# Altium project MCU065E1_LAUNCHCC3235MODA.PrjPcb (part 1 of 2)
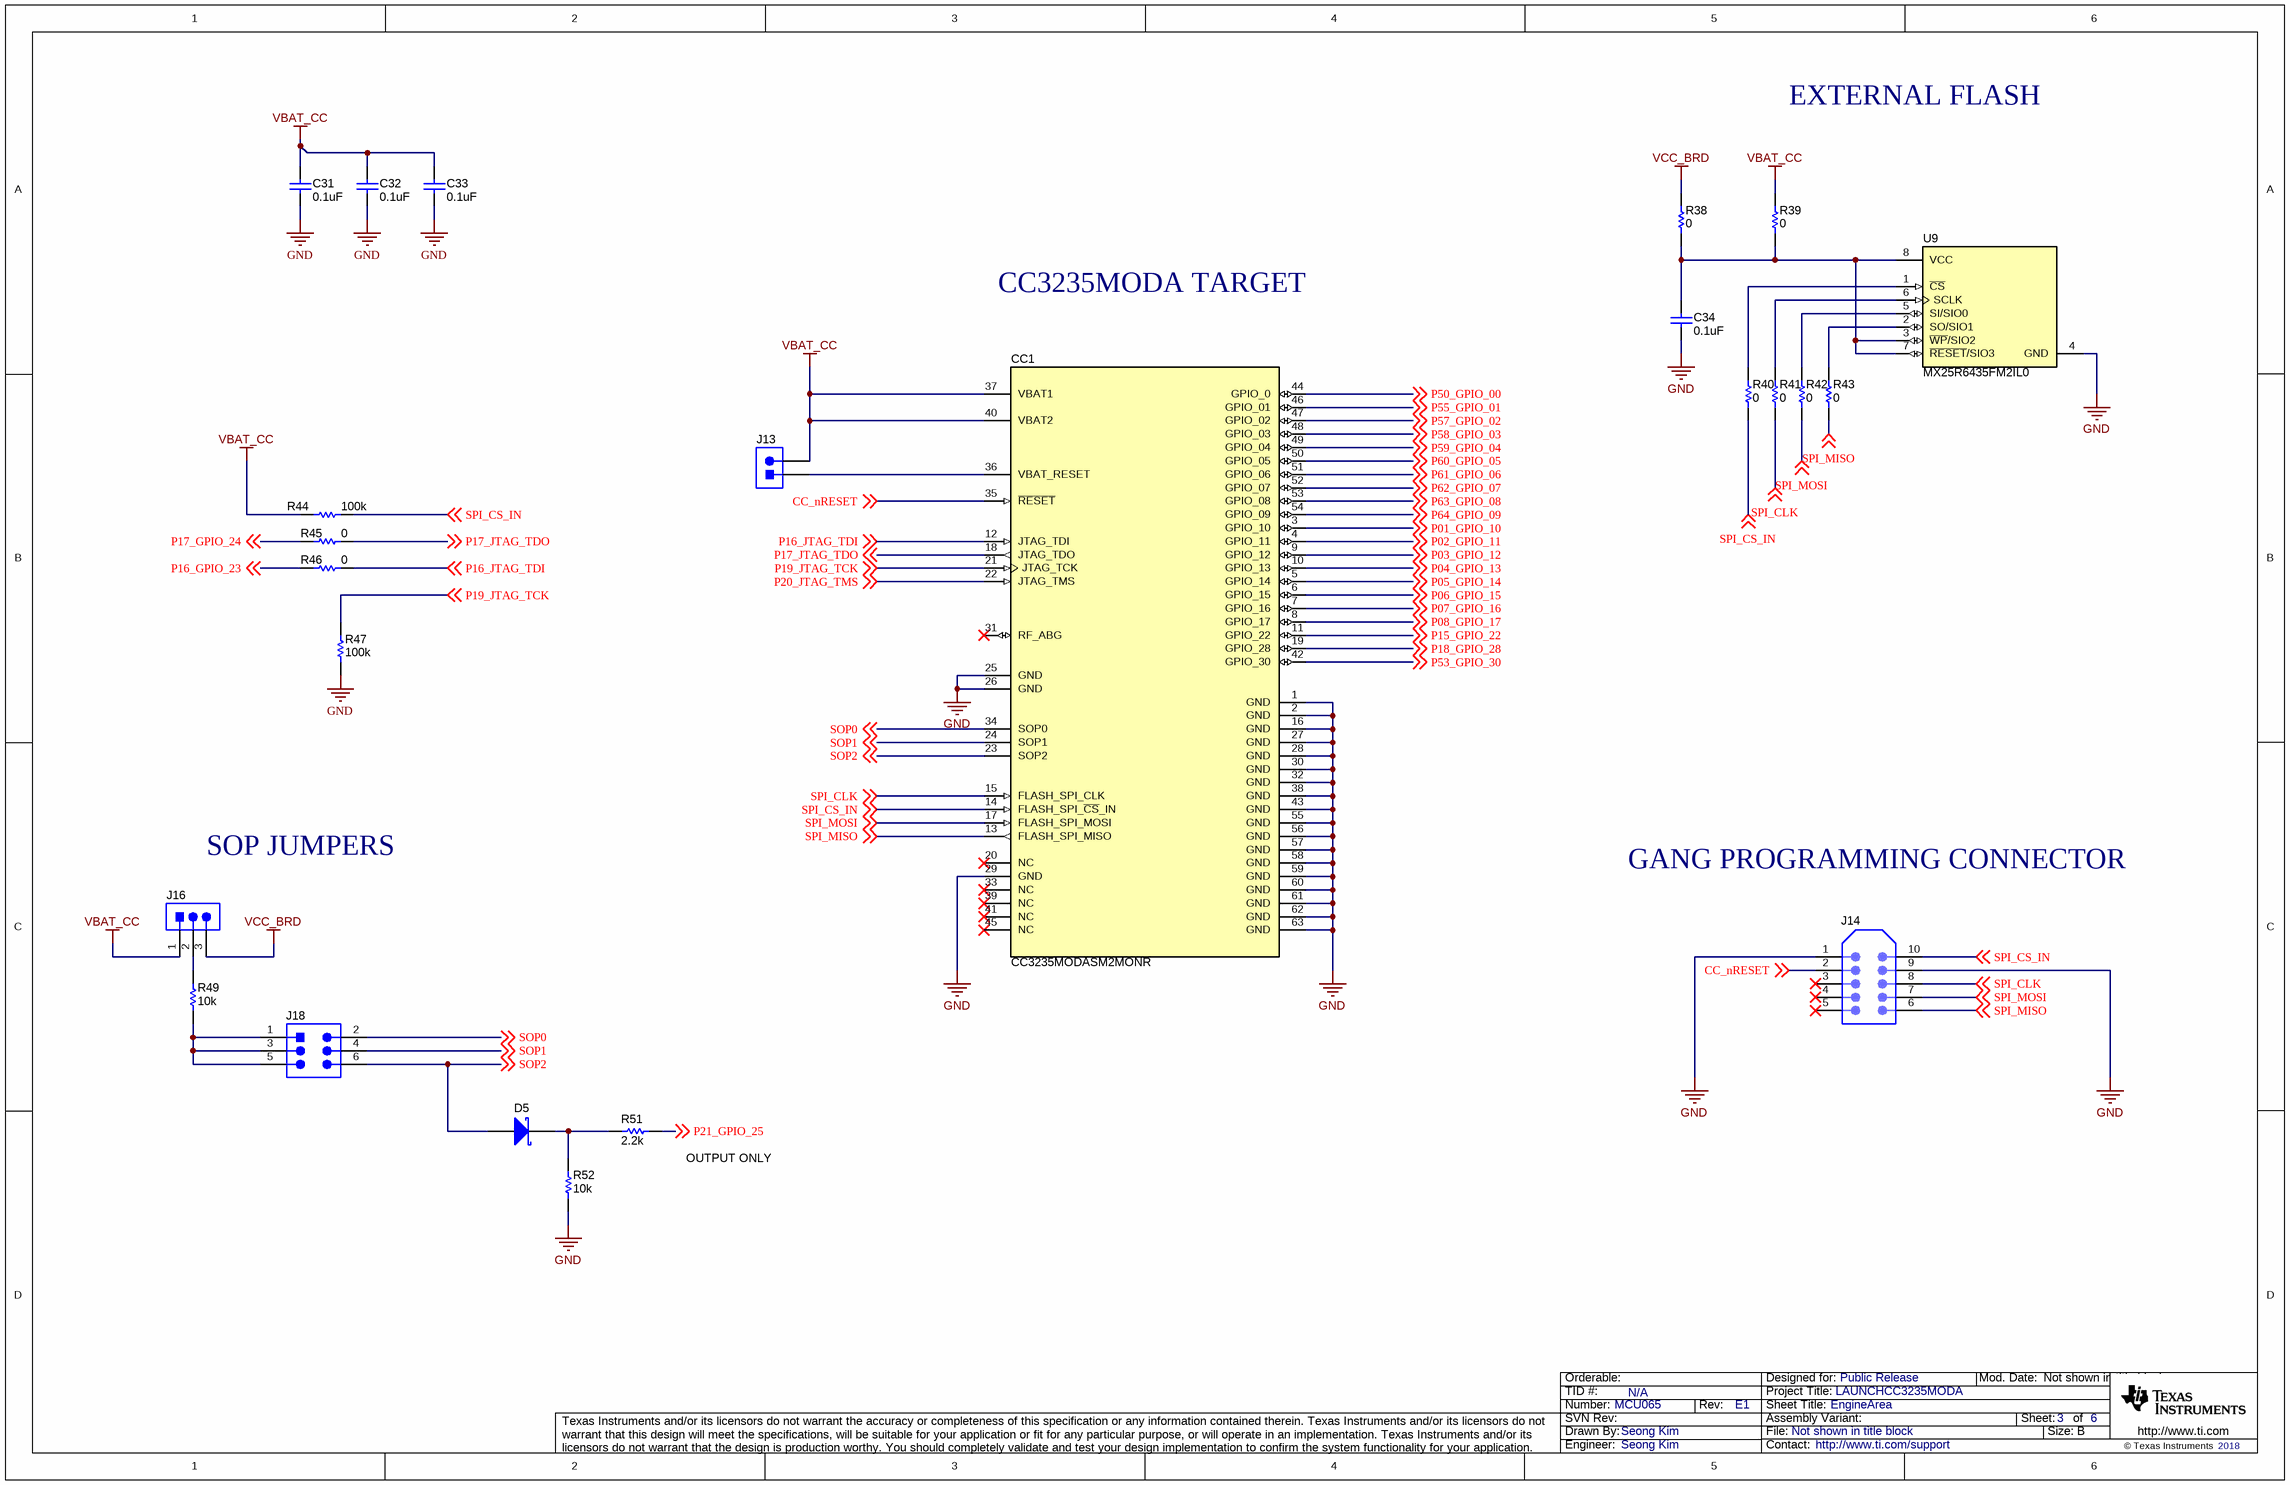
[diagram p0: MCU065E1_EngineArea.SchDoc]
CopyrightYear: 2018; PCB_Layout: Seong Kim; PCB_Rev: E1; PRJ_Customer: Public Release; PRJ_Engineer: Seong Kim; PRJ_Number: MCU065; PRJ_Title: LAUNCHCC3235MODA; SCH_Rev: E1; TechSupport: http://www.ti.com/support; TID: N/A
6 sheets, 301 parts. Net scope: global (net labels, ports and power ports of the same name join across sheets).
Board file: MCU065E1_LAUNCHCC3235MODA_PCB.PcbDoc
Sheets:
  MCU065E1_EngineArea.SchDoc
  MCU065E1_Hardware.SchDoc
  MCU065E1_Host_Interface.SchDoc
  MCU065E1_LEDs_Switches_Sensors.SchDoc
  MCU065E1_XDS110_Circuit.SchDoc
  MCU065E1_XDS110_Host.SchDoc

## Sheet MCU065E1_EngineArea.SchDoc: EngineArea
size 431 x 279 mm; Date: Not shown in title block; ApprovedBy: Not shown in title block; CheckedBy: Not shown in title block; Author: Not shown in title block; CompanyName: Not shown in title block; DrawnBy: Seong Kim; Engineer: Not shown in title block; Organization: Not shown in title block; Address1: Not shown in title block; Address2: Not shown in title block; Address3: Not shown in title block; Address4: Not shown in title block; DocumentNumber: 3; Revision: Use project parameter SCH_Rev; SheetNumber: 3; SheetTotal: 6; PageSetup: Record=PageOptions¦CenterHorizontal=True¦CenterVertical=True¦PrintScale=1.00¦XCorrection=1.00¦YCorrection=1.00¦PrintKind=0¦BorderSize=5000000¦LeftOffset=0¦BottomOffset=0¦Orientation=2¦PaperLength=1000¦PaperWidth=1000¦Scale=100¦PaperSource=15¦PrintQuality=600¦MediaType=1¦DitherType=10¦PaperKind=Letter¦PrintScaleMode=1

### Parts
C31  ValueDisplayed: 0.1uF  [0402]  (hidden comment: GRM155R61A104KA01D)
C32  ValueDisplayed: 0.1uF  [0402]  (hidden comment: GRM155R61A104KA01D)
C33  ValueDisplayed: 0.1uF  [0402]  (hidden comment: GRM155R61A104KA01D)
C34  ValueDisplayed: 0.1uF  [0402]  (hidden comment: GRM155R61A104KA01D)
CC1  CC3235MODASM2MONR  [MON0063A]
D5  CDBU00340  [SOD-523F]  (value not drawn)
J13  961102-6404-AR  [3M_961102-6404-AR]  (value not drawn)
J14  TC2050-IDC-NL-FP  [Tag_TC2050-NL]  (value not drawn)  (no BOM)
J16  CMP-0054796-1  [WURTH_61300311121]  (value not drawn)
J18  61300621121  [Wurth_61300621121]  (value not drawn)
R38  ValueDisplayed: 0  [0402]  (hidden comment: ERJ-2GE0R00X)
R39  ValueDisplayed: 0  [0402]  (hidden comment: ERJ-2GE0R00X)
R40  ValueDisplayed: 0  [0402]  (hidden comment: ERJ-2GE0R00X)
R41  ValueDisplayed: 0  [0402]  (hidden comment: ERJ-2GE0R00X)
R42  ValueDisplayed: 0  [0402]  (hidden comment: ERJ-2GE0R00X)
R43  ValueDisplayed: 0  [0402]  (hidden comment: ERJ-2GE0R00X)
R44  ValueDisplayed: 100k  [0402]  (hidden comment: CRCW0402100KDHEDP)
R45  ValueDisplayed: 0  [0402]  (hidden comment: ERJ-2GE0R00X)
R46  ValueDisplayed: 0  [0402]  (hidden comment: ERJ-2GE0R00X)
R47  ValueDisplayed: 100k  [0402]  (hidden comment: CRCW0402100KJNED)
R49  ValueDisplayed: 10k  [0402]  (hidden comment: CRCW040210K0JNED)
R51  ValueDisplayed: 2.2k  [0402]  (hidden comment: CRCW04022K20JNED)
R52  ValueDisplayed: 10k  [0402]  (hidden comment: CRCW040210K0JNED)
U9  MX25R6435FM2IL0  [SOP-8_200MIL]

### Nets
GND: C31.2 C32.2 C33.2 C34.2 CC1.1(GND) CC1.2(GND) CC1.16(GND) CC1.25(GND) CC1.26(GND) CC1.27(GND) CC1.28(GND) CC1.29(GND) CC1.30(GND) CC1.32(GND) CC1.38(GND) CC1.43(GND) CC1.55(GND) CC1.56(GND) CC1.57(GND) CC1.58(GND) CC1.59(GND) CC1.60(GND) CC1.61(GND) CC1.62(GND) CC1.63(GND) J14.1 J14.9 R47.1 R52.1 U9.4(GND)
VBAT_CC: C31.1 C32.1 C33.1 CC1.37(VBAT1) CC1.40(VBAT2) J13.2 J16.1 R39.2 R44.1
VCC_BRD: J16.3 R38.2
CC_nRESET: CC1.35(~{RESET}) J14.2 ; off-sheet CC_nRESET
P01_GPIO_10: CC1.3(GPIO_10) ; off-sheet P01_GPIO_10
P02_GPIO_11: CC1.4(GPIO_11) ; off-sheet P02_GPIO_11
P03_GPIO_12: CC1.9(GPIO_12) ; off-sheet P03_GPIO_12
P04_GPIO_13: CC1.10(GPIO_13) ; off-sheet P04_GPIO_13
P05_GPIO_14: CC1.5(GPIO_14) ; off-sheet P05_GPIO_14
P06_GPIO_15: CC1.6(GPIO_15) ; off-sheet P06_GPIO_15
P07_GPIO_16: CC1.7(GPIO_16) ; off-sheet P07_GPIO_16
P08_GPIO_17: CC1.8(GPIO_17) ; off-sheet P08_GPIO_17
P15_GPIO_22: CC1.11(GPIO_22) ; off-sheet P15_GPIO_22
P16_GPIO_23: R46.1 ; off-sheet P16_GPIO_23
P16_JTAG_TDI: CC1.12(JTAG_TDI) R46.2 ; off-sheet P16_JTAG_TDI
P17_GPIO_24: R45.1 ; off-sheet P17_GPIO_24
P17_JTAG_TDO: CC1.18(JTAG_TDO) R45.2 ; off-sheet P17_JTAG_TDO
P18_GPIO_28: CC1.19(GPIO_28) ; off-sheet P18_GPIO_28
P19_JTAG_TCK: CC1.21(JTAG_TCK) R47.2 ; off-sheet P19_JTAG_TCK
P20_JTAG_TMS: CC1.22(JTAG_TMS) ; off-sheet P20_JTAG_TMS
P21_GPIO_25: R51.2 ; off-sheet P21_GPIO_25
P50_GPIO_00: CC1.44(GPIO_0) ; off-sheet P50_GPIO_00
P53_GPIO_30: CC1.42(GPIO_30) ; off-sheet P53_GPIO_30
P55_GPIO_01: CC1.46(GPIO_01) ; off-sheet P55_GPIO_01
P57_GPIO_02: CC1.47(GPIO_02) ; off-sheet P57_GPIO_02
P58_GPIO_03: CC1.48(GPIO_03) ; off-sheet P58_GPIO_03
P59_GPIO_04: CC1.49(GPIO_04) ; off-sheet P59_GPIO_04
P60_GPIO_05: CC1.50(GPIO_05) ; off-sheet P60_GPIO_05
P61_GPIO_06: CC1.51(GPIO_06) ; off-sheet P61_GPIO_06
P62_GPIO_07: CC1.52(GPIO_07) ; off-sheet P62_GPIO_07
P63_GPIO_08: CC1.53(GPIO_08) ; off-sheet P63_GPIO_08
P64_GPIO_09: CC1.54(GPIO_09) ; off-sheet P64_GPIO_09
SOP0: CC1.34(SOP0) J18.2 ; off-sheet SOP0
SOP1: CC1.24(SOP1) J18.4 ; off-sheet SOP1
SOP2: CC1.23(SOP2) D5.2(A) J18.6 ; off-sheet SOP2
SPI_CLK: CC1.15(FLASH_SPI_CLK) J14.8 R41.1 ; off-sheet SPI_CLK
SPI_CS_IN: CC1.14(FLASH_SPI_~{CS}_IN) J14.10 R40.1 R44.2 ; off-sheet SPI_CS_IN
SPI_MISO: CC1.13(FLASH_SPI_MISO) J14.6 R43.1 ; off-sheet SPI_MISO
SPI_MOSI: CC1.17(FLASH_SPI_MOSI) J14.7 R42.1 ; off-sheet SPI_MOSI
NetC34_1: C34.1 R38.1 R39.1 U9.3(~{WP}/SIO2) U9.7(~{RESET}/SIO3) U9.8(VCC)
NetCC1_36: CC1.36(VBAT_RESET) J13.1
NetD5_1: D5.1(K) R51.1 R52.2
NetJ16_2: J16.2 R49.2
NetJ18_1: J18.1 J18.3 J18.5 R49.1
NetR40_2: R40.2 U9.1(~{CS})
NetR41_2: R41.2 U9.6(SCLK)
NetR42_2: R42.2 U9.5(SI/SIO0)
NetR43_2: R43.2 U9.2(SO/SIO1)

Not connected (* = marked no-connect by the designer): CC1 20(NC)* 31(RF_ABG)* 33(NC)* 39(NC)* 41(NC)* 45(NC)*; J14 3* 4* 5*

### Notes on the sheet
- EXTERNAL FLASH
- CC3235MODA TARGET
- SOP JUMPERS
- GANG PROGRAMMING CONNECTOR
- (near R51) OUTPUT ONLY

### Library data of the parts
C31-C34 = CMP-0006562-2: CAP, CERM, 0.1 uF, 10 V, +/- 10%, X5R, 0402; Manufacturer: MuRata; TaMin_C: -55°C; Polarized: N; SizeAreaWB_mm2: 3; Value1: Unknown; U/M: EA; Value: 0.1uF; TaMax_C: 85°C; SizeZ_mm: 0.6; SizeX_mm: 1; SizeY_mm: 0.5; Value2: 10V; CompType: Capacitor; Cap_F: 100nF; AEC Category: Q200
CC1 = CMP-0085200-1: SimpleLink Wi-FI and Internet-of-Things Dual Band Module Solution, a Single-Chip Wireless MCU, MON0063A (QFM-63); Alternate Manufacturer: Texas Instruments; SizeX_mm: 25.5; AEC Category: Q200; CompType: IC; SizeArea_mm2: 522.75; SizeY_mm: 20.5; SizeZ_mm: 2.45; AEC Qualified: N; SizeAreaWB_mm2: 618.75
D5 = CMP-0081923-1: Diode, Schottky, 45 V, 0.03 A, SOD-523F; Manufacturer: Comchip Technology; Io_A: 30mA; SizeAreaWB_mm2: 5.13; Vr_V: 45V; Value1: 0.03A; TJmax_C: 125°C; Value: 45V; SizeZ_mm: 0.85; SizeX_mm: 1.7; SizeY_mm: 0.9; Vf_V: 370mV; Value2: 0.37V; SizeArea_mm2: 1.53; AEC Qualified: N; AEC Category: Q101
J13 = CMP-0075197-1: Header, 2.54mm, 2x1, TH; Manufacturer: 3M; CNHeader: True; Current_A: 2A; Green_Lifecycle: Active; Shrouded: N; Gender: Male; Green_REACh: Passed; Voltage_V: 1kV; Row_Count: 1; Pitch_mm: 2.54; ContactFinish: Gold; CT: False; Cert_UL: Y
J14 = CMP-0075101-1: Footprint for Tag-Connect TC2050 No-Legs cables; Note: Footprint only, to mate with Tag-Connect TC2050 No-Legs cables; CT: False; CompType: Receptacle
J16 = CMP-0054796-1: Header, 2.54 mm, 3x1, Gold, TH; PartNumber: 61300311121; Manufacturer: Wurth Elektronik; CNHeader: TRUE; Green_Lifecycle: Active; Green_REACh: Passed; CT: FALSE
J18 = CMP-0054802-2: Header, 2.54mm, 3x2, Gold, TH; Manufacturer: Wurth Elektronik; Green_Lifecycle: Active; Shrouded: N; Gender: Male; Green_REACh: Passed; Row_Count: 2; RowSpacing_mm: 2.54
R38-R43 R45 R46 = CMP-0026992-3: RES, 0, 5%, 0.1 W, AEC-Q200 Grade 0, 0402; Manufacturer: Panasonic; Power_W: 100mW; TempCo: 600 ppm/C; Value_Code: 0000; Value: 0; EIA_Code: E24; SizeX_mm: 1; SizeY_mm: 0.5; SizeZ_mm: 0.6; Value2: 0.1W; CompType: Resistor; AEC Qualified: Y; VDC_V: 50V; AEC Category: Q200; SizeAreaWB_mm2: 3
R44 = CMP-0026768-2: RES, 100 k, 0.5%, 0.063 W, AEC-Q200 Grade 0, 0402; Manufacturer: Vishay-Dale; Power_W: 63mW; TempCo: 50 ppm/C; Value: 100k; EIA_Code: E192; SizeX_mm: 1; SizeY_mm: 0.5; SizeZ_mm: 0.6; Value2: 0.063W; CompType: Resistor; AEC Qualified: Y; VDC_V: 50V; AEC Category: Q200; AEC Grade: 0
R47 = CMP-0026823-3: RES, 100 k, 5%, 0.063 W, AEC-Q200 Grade 0, 0402; Manufacturer: Vishay-Dale; Power_W: 63mW; TempCo: 200 ppm/C; Value: 100k; EIA_Code: E24; SizeX_mm: 1; SizeY_mm: 0.5; SizeZ_mm: 0.6; Value2: 0.063W; CompType: Resistor; AEC Qualified: Y; VDC_V: 50V; AEC Category: Q200; AEC Grade: 0
R49 R52 = CMP-0026825-5: RES, 10 k, 5%, 0.063 W, AEC-Q200 Grade 0, 0402; Manufacturer: Vishay-Dale; Power_W: 63mW; TempCo: 200 ppm/C; Value_Code: 10k0; Value: 10k; EIA_Code: E24; SizeX_mm: 1; SizeY_mm: 0.5; SizeZ_mm: 0.6; Value2: 0.063W; CompType: Resistor; AEC Qualified: Y; VDC_V: 50V; AEC Category: Q200; AEC Grade: 0
R51 = CMP-0026890-5: RES, 2.2 k, 5%, 0.063 W, AEC-Q200 Grade 0, 0402; Manufacturer: Vishay-Dale; Power_W: 63mW; TempCo: 200 ppm/C; Value_Code: 2k20; Value: 2.2k; EIA_Code: E24; SizeX_mm: 1; SizeY_mm: 0.5; SizeZ_mm: 0.6; Value2: 0.063W; CompType: Resistor; AEC Qualified: Y; VDC_V: 50V; AEC Category: Q200; AEC Grade: 0
U9 = CMP-0004983-1: ULTRA LOW POWER, 64M-BIT [x 1/x 2/x 4] CMOS MXSMIO (SERIAL MULTI I/O) FLASH MEMORY, SOP-8; Manufacturer: Macronix International Co., LTD; SizeZ_mm: 2.16; SizeX_mm: 7.9; SizeY_mm: 5.23; SizeArea_mm2: 41.317; SizeAreaWB_mm2: 71.577

## Sheet MCU065E1_Hardware.SchDoc: Hardware
size 431 x 279 mm; Date: Not shown in title block; ApprovedBy: Not shown in title block; CheckedBy: Not shown in title block; Author: Not shown in title block; CompanyName: Not shown in title block; DrawnBy: Seong Kim; Engineer: Not shown in title block; Organization: Not shown in title block; Address1: Not shown in title block; Address2: Not shown in title block; Address3: Not shown in title block; Address4: Not shown in title block; DocumentNumber: 6; Revision: Use project parameter SCH_Rev; SheetNumber: 6; SheetTotal: 6; PageSetup: Record=PageOptions¦CenterHorizontal=True¦CenterVertical=True¦PrintScale=1.00¦XCorrection=1.00¦YCorrection=1.00¦PrintKind=0¦BorderSize=5000000¦LeftOffset=0¦BottomOffset=0¦Orientation=2¦PaperLength=1000¦PaperWidth=1000¦Scale=100¦PaperSource=15¦PrintQuality=600¦MediaType=1¦DitherType=10¦PaperKind=Letter¦PrintScaleMode=1
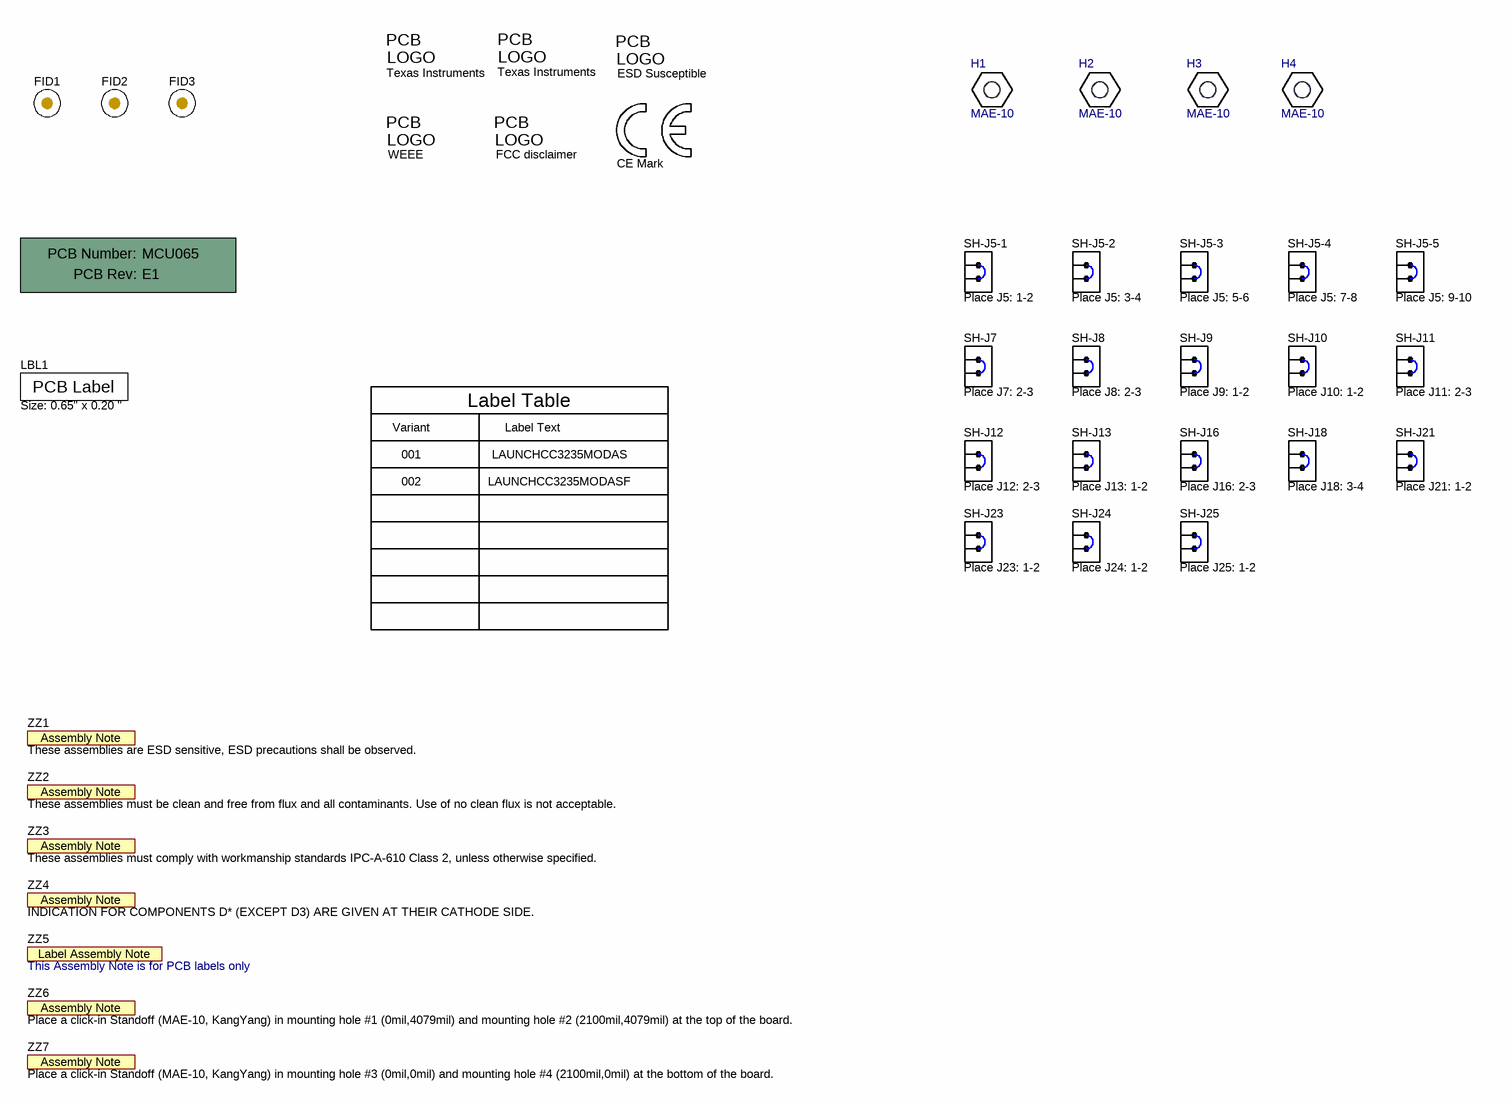
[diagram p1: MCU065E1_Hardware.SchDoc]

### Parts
!PCB1  Printed Circuit Board  (value not drawn)  (mechanical)
CE_Logo_1  CE Mark  [CE_Mark_5mm]  (no BOM)
FID1  CMP-0077181-1  [Fiducial10-20]  (value not drawn)  (no BOM)
FID2  CMP-0077181-1  [Fiducial10-20]  (value not drawn)  (no BOM)
FID3  CMP-0077181-1  [Fiducial10-20]  (value not drawn)  (no BOM)
H1  MAE-10  [KY_MAE-10]
H2  MAE-10  [KY_MAE-10]
H3  MAE-10  [KY_MAE-10]
H4  MAE-10  [KY_MAE-10]
LBL1  Size: 0.65" x 0.20 "  [Label_650x200]
Logo1  Texas Instruments  [TI_Symbol_Overlay_Medium]  (no BOM)
Logo2  ESD Susceptible  [ESD_Overlay_Medium]  (no BOM)
Logo3  WEEE  [WEEE_Minimum]  (no BOM)
Logo4  FCC disclaimer  [FCC_disclaimer]  (no BOM)
SH-J5-1  Place J5: 1-2  [SNT-100-BK-G]
SH-J5-2  Place J5: 3-4  [SNT-100-BK-G]
SH-J5-3  Place J5: 5-6  [SNT-100-BK-G]
SH-J5-4  Place J5: 7-8  [SNT-100-BK-G]
SH-J5-5  Place J5: 9-10  [SNT-100-BK-G]
SH-J7  Place J7: 2-3  [SNT-100-BK-G]
SH-J8  Place J8: 2-3  [SNT-100-BK-G]
SH-J9  Place J9: 1-2  [SNT-100-BK-G]
SH-J10  Place J10: 1-2  [SNT-100-BK-G]
SH-J11  Place J11: 2-3  [SNT-100-BK-G]
SH-J12  Place J12: 2-3  [SNT-100-BK-G]
SH-J13  Place J13: 1-2  [SNT-100-BK-G]
SH-J16  Place J16: 2-3  [SNT-100-BK-G]
SH-J18  Place J18: 3-4  [SNT-100-BK-G]
SH-J21  Place J21: 1-2  [SNT-100-BK-G]
SH-J23  Place J23: 1-2  [SNT-100-BK-G]
SH-J24  Place J24: 1-2  [SNT-100-BK-G]
SH-J25  Place J25: 1-2  [SNT-100-BK-G]
TI_Logo_1  Texas Instruments  [TI_Stacked_Overlay_Medium]  (no BOM)
ZZ1  These assemblies are ESD sensitive, ESD precautions shall be observed.  [AssemblyNote]  (no BOM)
ZZ2  These assemblies must be clean and free from flux and all contaminants. Use of no clean flux is not acceptable.  [AssemblyNote]  (no BOM)
ZZ3  These assemblies must comply with workmanship standards IPC-A-610 Class 2, unless otherwise specified.  [AssemblyNote]  (no BOM)
ZZ4  INDICATION FOR COMPONENTS D* (EXCEPT D3) ARE GIVEN AT THEIR CATHODE SIDE.  [AssemblyNote]  (no BOM)
ZZ5  This Assembly Note is for PCB labels only  [AssemblyNoteLabel]  (no BOM)
ZZ6  Place a click-in Standoff (MAE-10, KangYang) in mounting hole #1 (0mil,4079mil) and mounting hole #2 (2100mil,4079mil) at the top of the board.  [AssemblyNote]  (no BOM)
ZZ7  Place a click-in Standoff (MAE-10, KangYang) in mounting hole #3 (0mil,0mil) and mounting hole #4 (2100mil,0mil) at the bottom of the board.  [AssemblyNote]  (no BOM)

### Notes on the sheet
- Label Table
- Variant
- 001
- Label Text
- LAUNCHCC3235MODAS
- 002
- LAUNCHCC3235MODASF

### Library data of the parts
!PCB1 = CMP-0003618-2: PartNumber: MCU065; Manufacturer: Any; CompType: PCB
CE_Logo_1 = CMP-0074844-1: SymbolCreator: a0412235
FID1-FID3 = CMP-0077181-1: Fiducial mark.  There is nothing to buy or mount.
H1-H4 = CMP-0077978-1: Spacer Support, Nylon 66; Manufacturer: Kang Yang; CompType: Standoff
LBL1 = CMP-0003625-1: Manufacturer: Brady; Key: THT-14-423-10; CompType: Label
Logo1 TI_Logo_1 = CMP-0074838-1: Texas Instrument Corporate Signature; Library Reference: Logo; SymbolCreator: a0412235; Lib Reference: TI_Logo
Logo2 = CMP-0074840-1: ESD Susceptible Symbol; Library Reference: Logo; SymbolCreator: a0412235; Lib Reference: ESD_Susceptible
Logo3 = CMP-0074769-1: WEEE logo
Logo4 = CMP-0074847-1: FCC_disclaimer; Library Reference: Logo
SH-J5-1-SH-J5-5 SH-J7-SH-J13 SH-J16 SH-J18 SH-J21 SH-J23-SH-J25 = CMP-0003623-3: Shunt, 100mil, Gold plated, Black; Alternate PartNumber: 969102-0000-DA; Manufacturer: Samtec; Alternate Manufacturer: 3M; Value: 1x2
ZZ1-ZZ3 = CMP-0077238-1: This Assembly Note will show in the PcbDoc and associated outputs
ZZ4 ZZ6 ZZ7 = CMP-0077238-1
ZZ5 = CMP-0003616-3

## Sheet MCU065E1_Host_Interface.SchDoc: Host_Interface
size 431 x 279 mm; Date: Not shown in title block; ApprovedBy: Not shown in title block; CheckedBy: Not shown in title block; Author: Not shown in title block; CompanyName: Not shown in title block; DrawnBy: Seong Kim; Engineer: Not shown in title block; Organization: Not shown in title block; Address1: Not shown in title block; Address2: Not shown in title block; Address3: Not shown in title block; Address4: Not shown in title block; DocumentNumber: 5; Revision: Use project parameter SCH_Rev; SheetNumber: 5; SheetTotal: 6; PageSetup: Record=PageOptions¦CenterHorizontal=True¦CenterVertical=True¦PrintScale=1.00¦XCorrection=1.00¦YCorrection=1.00¦PrintKind=0¦BorderSize=5000000¦LeftOffset=0¦BottomOffset=0¦Orientation=2¦PaperLength=1000¦PaperWidth=1000¦Scale=100¦PaperSource=15¦PrintQuality=600¦MediaType=1¦DitherType=10¦PaperKind=Letter¦PrintScaleMode=1
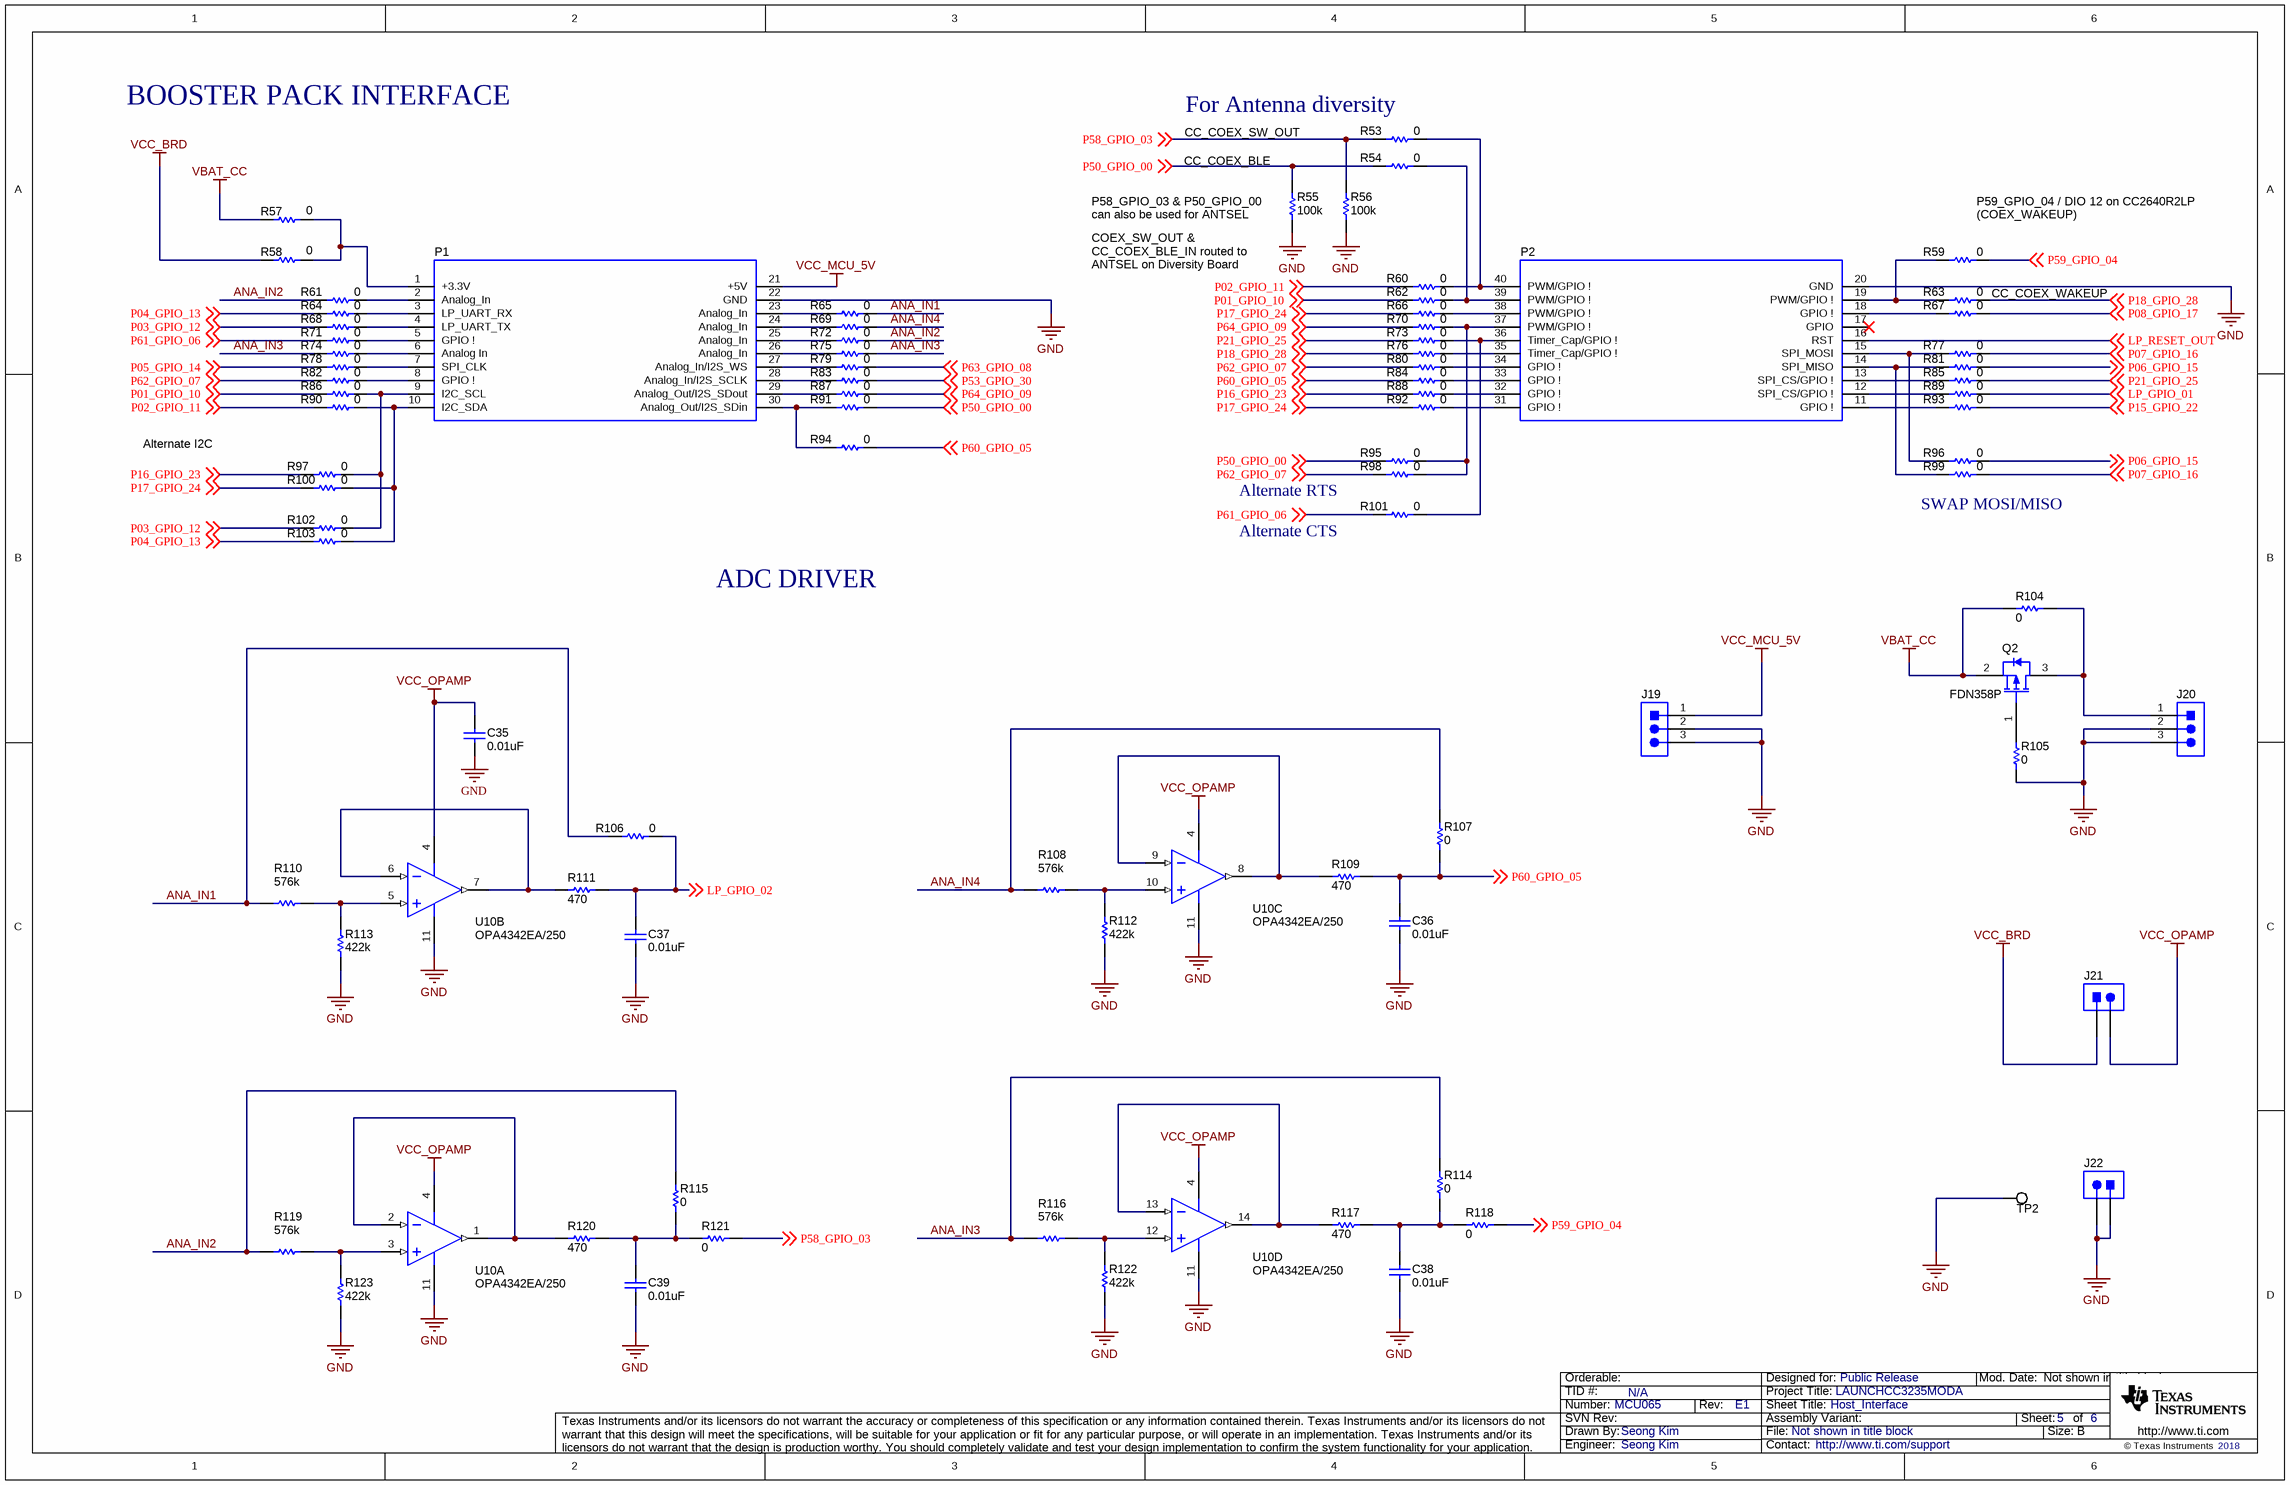
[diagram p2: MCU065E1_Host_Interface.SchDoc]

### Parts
C35  ValueDisplayed: 0.01uF  [0402]  (hidden comment: GRM155R61A103KA01D)
C36  ValueDisplayed: 0.01uF  [0402]  (hidden comment: GRM155R71C103KA01D)
C37  ValueDisplayed: 0.01uF  [0402]  (hidden comment: GRM155R71C103KA01D)
C38  ValueDisplayed: 0.01uF  [0402]  (hidden comment: GRM155R71C103KA01D)
C39  ValueDisplayed: 0.01uF  [0402]  (hidden comment: GRM155R71C103KA01D)
J19  PEC03SAAN  [CONN_PEC03SAAN]  (value not drawn)
J20  PEC03SAAN  [CONN_PEC03SAAN]  (value not drawn)
J21  CMP-0054794-1  [WURTH_61300211121]  (value not drawn)
J22  61300211121  [WURTH_61300211121]  (value not drawn)
P1  SSQ-110-03-T-D  [BoosterPack_40pin_J1J3]  (value not drawn)
P2  SSQ-110-03-T-D  [BoosterPack_40pin_J2J4]  (value not drawn)
Q2  FDN358P  [SSOT-3]
R53  ValueDisplayed: 0  [0402]  (hidden comment: RC0402JR-070RL)
R54  ValueDisplayed: 0  [0402]  (hidden comment: RC0402JR-070RL)
R55  ValueDisplayed: 100k  [0402]  (hidden comment: CMP-0026823-3)
R56  ValueDisplayed: 100k  [0402]  (hidden comment: CMP-0026823-3)
R57  ValueDisplayed: 0  [0603]  (hidden comment: CMP-0025874-3)
R58  ValueDisplayed: 0  [0603]  (hidden comment: CMP-0025874-3)
R59  ValueDisplayed: 0  [0402]  (hidden comment: RC0402JR-070RL)
R60  ValueDisplayed: 0  [0402]  (hidden comment: RC0402JR-070RL)
R61  ValueDisplayed: 0  [0402]  (hidden comment: RC0402JR-070RL)
R62  ValueDisplayed: 0  [0402]  (hidden comment: RC0402JR-070RL)
R63  ValueDisplayed: 0  [0402]  (hidden comment: RC0402JR-070RL)
R64  ValueDisplayed: 0  [0402]  (hidden comment: RC0402JR-070RL)
R65  ValueDisplayed: 0  [0402]  (hidden comment: RC0402JR-070RL)
R66  ValueDisplayed: 0  [0402]  (hidden comment: RC0402JR-070RL)
R67  ValueDisplayed: 0  [0402]  (hidden comment: RC0402JR-070RL)
R68  ValueDisplayed: 0  [0402]  (hidden comment: RC0402JR-070RL)
R69  ValueDisplayed: 0  [0402]  (hidden comment: RC0402JR-070RL)
R70  ValueDisplayed: 0  [0402]  (hidden comment: RC0402JR-070RL)
R71  ValueDisplayed: 0  [0402]  (hidden comment: RC0402JR-070RL)
R72  ValueDisplayed: 0  [0402]  (hidden comment: RC0402JR-070RL)
R73  ValueDisplayed: 0  [0402]  (hidden comment: RC0402JR-070RL)
R74  ValueDisplayed: 0  [0402]  (hidden comment: RC0402JR-070RL)
R75  ValueDisplayed: 0  [0402]  (hidden comment: RC0402JR-070RL)
R76  ValueDisplayed: 0  [0402]  (hidden comment: RC0402JR-070RL)
R77  ValueDisplayed: 0  [0402]  (hidden comment: RC0402JR-070RL)
R78  ValueDisplayed: 0  [0402]  (hidden comment: RC0402JR-070RL)
R79  ValueDisplayed: 0  [0402]  (hidden comment: RC0402JR-070RL)
R80  ValueDisplayed: 0  [0402]  (hidden comment: RC0402JR-070RL)
R81  ValueDisplayed: 0  [0402]  (hidden comment: RC0402JR-070RL)
R82  ValueDisplayed: 0  [0402]  (hidden comment: RC0402JR-070RL)
R83  ValueDisplayed: 0  [0402]  (hidden comment: RC0402JR-070RL)
R84  ValueDisplayed: 0  [0402]  (hidden comment: RC0402JR-070RL)
R85  ValueDisplayed: 0  [0402]  (hidden comment: RC0402JR-070RL)
R86  ValueDisplayed: 0  [0402]  (hidden comment: RC0402JR-070RL)
R87  ValueDisplayed: 0  [0402]  (hidden comment: RC0402JR-070RL)
R88  ValueDisplayed: 0  [0402]  (hidden comment: RC0402JR-070RL)
R89  ValueDisplayed: 0  [0402]  (hidden comment: RC0402JR-070RL)
R90  ValueDisplayed: 0  [0402]  (hidden comment: RC0402JR-070RL)
R91  ValueDisplayed: 0  [0402]  (hidden comment: RC0402JR-070RL)
R92  ValueDisplayed: 0  [0402]  (hidden comment: RC0402JR-070RL)
R93  ValueDisplayed: 0  [0402]  (hidden comment: RC0402JR-070RL)
R94  ValueDisplayed: 0  [0402]  (hidden comment: RC0402JR-070RL)
R95  ValueDisplayed: 0  [0402]  (hidden comment: RC0402JR-070RL)
R96  ValueDisplayed: 0  [0402]  (hidden comment: RC0402JR-070RL)
R97  ValueDisplayed: 0  [0402]  (hidden comment: RC0402JR-070RL)
R98  ValueDisplayed: 0  [0402]  (hidden comment: RC0402JR-070RL)
R99  ValueDisplayed: 0  [0402]  (hidden comment: RC0402JR-070RL)
R100  ValueDisplayed: 0  [0402]  (hidden comment: RC0402JR-070RL)
R101  ValueDisplayed: 0  [0402]  (hidden comment: RC0402JR-070RL)
R102  ValueDisplayed: 0  [0402]  (hidden comment: RC0402JR-070RL)
R103  ValueDisplayed: 0  [0402]  (hidden comment: RC0402JR-070RL)
R104  ValueDisplayed: 0  [0402]  (hidden comment: ERJ-2GE0R00X)
R105  ValueDisplayed: 0  [0402]  (hidden comment: ERJ-2GE0R00X)
R106  ValueDisplayed: 0  [0402]  (hidden comment: RC0402JR-070RL)
R107  ValueDisplayed: 0  [0402]  (hidden comment: RC0402JR-070RL)
R108  ValueDisplayed: 576k  [0402]  (hidden comment: CRCW0402576KFKED)
R109  ValueDisplayed: 470  [0402]  (hidden comment: ERJ-2RKF4700X)
R110  ValueDisplayed: 576k  [0402]  (hidden comment: CRCW0402576KFKED)
R111  ValueDisplayed: 470  [0402]  (hidden comment: ERJ-2RKF4700X)
R112  ValueDisplayed: 422k  [0402]  (hidden comment: CRCW0402422KFKED)
R113  ValueDisplayed: 422k  [0402]  (hidden comment: CRCW0402422KFKED)
R114  ValueDisplayed: 0  [0402]  (hidden comment: RC0402JR-070RL)
R115  ValueDisplayed: 0  [0402]  (hidden comment: RC0402JR-070RL)
R116  ValueDisplayed: 576k  [0402]  (hidden comment: CRCW0402576KFKED)
R117  ValueDisplayed: 470  [0402]  (hidden comment: ERJ-2RKF4700X)
R118  ValueDisplayed: 0  [0402]  (hidden comment: RC0402JR-070RL)
R119  ValueDisplayed: 576k  [0402]  (hidden comment: CRCW0402576KFKED)
R120  ValueDisplayed: 470  [0402]  (hidden comment: ERJ-2RKF4700X)
R121  ValueDisplayed: 0  [0402]  (hidden comment: RC0402JR-070RL)
R122  ValueDisplayed: 422k  [0402]  (hidden comment: CRCW0402422KFKED)
R123  ValueDisplayed: 422k  [0402]  (hidden comment: CRCW0402422KFKED)
TP2  5015  [Testpoint_Keystone_Miniature]  (value not drawn)
U10  OPA4342EA/250  [PW0014A_N]  (parts A,B,C,D of 4)

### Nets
GND: C35.2 C36.2 C37.2 C38.2 C39.2 J19.2 J19.3 J20.2 J20.3 J22.1 J22.2 P1.22(GND) P2.20(GND) R55.2 R56.2 R105.2 R112.1 R113.1 R122.1 R123.1 TP2.1 U10.11(V-)
VBAT_CC: Q2.2(S) R57.1 R104.2
VCC_BRD: J21.1 R58.1
VCC_MCU_5V: J19.1 P1.21(+5V)
VCC_OPAMP: C35.1 J21.2 U10.4(V+)
ANA_IN1: R65.2 R106.1 R110.1
ANA_IN2: R61.1 R72.2 R115.1 R119.1
ANA_IN3: R74.1 R75.2 R114.1 R116.1
ANA_IN4: R69.2 R107.1 R108.1
LP_GPIO_01: R89.2 ; off-sheet LP_GPIO_01
LP_GPIO_02: C37.1 R106.2 R111.2 ; off-sheet LP_GPIO_02
LP_RESET_OUT: P2.16(RST) ; off-sheet LP_RESET_OUT
P01_GPIO_10: R62.1 R86.1 ; off-sheet P01_GPIO_10
P02_GPIO_11: R60.1 R90.1 ; off-sheet P02_GPIO_11
P03_GPIO_12: R68.1 R102.1 ; off-sheet P03_GPIO_12
P04_GPIO_13: R64.1 R103.1 ; off-sheet P04_GPIO_13
P05_GPIO_14: R78.1 ; off-sheet P05_GPIO_14
P06_GPIO_15: R81.2 R96.2 ; off-sheet P06_GPIO_15
P07_GPIO_16: R77.2 R99.2 ; off-sheet P07_GPIO_16
P08_GPIO_17: R67.2 ; off-sheet P08_GPIO_17
P15_GPIO_22: R93.2 ; off-sheet P15_GPIO_22
P16_GPIO_23: R88.1 R97.1 ; off-sheet P16_GPIO_23
P17_GPIO_24: R66.1 R92.1 R100.1 ; off-sheet P17_GPIO_24
P18_GPIO_28: R63.2 R76.1 ; off-sheet P18_GPIO_28
P21_GPIO_25: R73.1 R85.2 ; off-sheet P21_GPIO_25
P50_GPIO_00: R54.1 R55.1 R91.2 R95.1 ; off-sheet P50_GPIO_00
P53_GPIO_30: R83.2 ; off-sheet P53_GPIO_30
P58_GPIO_03: R53.1 R56.1 R121.2 ; off-sheet P58_GPIO_03
P59_GPIO_04: R59.2 R118.2 ; off-sheet P59_GPIO_04
P60_GPIO_05: C36.1 R84.1 R94.2 R107.2 R109.2 ; off-sheet P60_GPIO_05
P61_GPIO_06: R71.1 R101.1 ; off-sheet P61_GPIO_06
P62_GPIO_07: R80.1 R82.1 R98.1 ; off-sheet P62_GPIO_07
P63_GPIO_08: R79.2 ; off-sheet P63_GPIO_08
P64_GPIO_09: R70.1 R87.2 ; off-sheet P64_GPIO_09
NetC38_1: C38.1 R114.2 R117.2 R118.1
NetC39_1: C39.1 R115.2 R120.2 R121.1
NetJ20_1: J20.1 Q2.3(D) R104.1
NetP1_1: P1.1(+3.3V) R57.2 R58.2
NetP1_2: P1.2(Analog_In) R61.2
NetP1_3: P1.3(LP_UART_RX) R64.2
NetP1_4: P1.4(LP_UART_TX) R68.2
NetP1_5: P1.5(GPIO_!) R71.2
NetP1_6: P1.6(Analog_In) R74.2
NetP1_7: P1.7(SPI_CLK) R78.2
NetP1_8: P1.8(GPIO_!) R82.2
NetP1_9: P1.9(I2C_SCL) R86.2 R97.2 R102.2
NetP1_10: P1.10(I2C_SDA) R90.2 R100.2 R103.2
NetP1_23: P1.23(Analog_In) R65.1
NetP1_24: P1.24(Analog_In) R69.1
NetP1_25: P1.25(Analog_In) R72.1
NetP1_26: P1.26(Analog_In) R75.1
NetP1_27: P1.27(Analog_In/I2S_WS) R79.1
NetP1_28: P1.28(Analog_In/I2S_SCLK) R83.1
NetP1_29: P1.29(Analog_Out/I2S_SDout) R87.1
NetP1_30: P1.30(Analog_Out/I2S_SDin) R91.1 R94.1
NetP2_11: P2.11(GPIO_!) R93.1
NetP2_12: P2.12(SPI_CS/GPIO_!) R89.1
NetP2_13: P2.13(SPI_CS/GPIO_!) R85.1
NetP2_14: P2.14(SPI_MISO) R81.1 R99.1
NetP2_15: P2.15(SPI_MOSI) R77.1 R96.1
NetP2_18: P2.18(GPIO_!) R67.1
NetP2_19: P2.19(PWM/GPIO_!) R59.1 R63.1
NetP2_31: P2.31(GPIO_!) R92.2
NetP2_32: P2.32(GPIO_!) R88.2
NetP2_33: P2.33(GPIO_!) R84.2
NetP2_34: P2.34(GPIO_!) R80.2
NetP2_35: P2.35(Timer_Cap/GPIO_!) R76.2
NetP2_36: P2.36(Timer_Cap/GPIO_!) R73.2 R101.2
NetP2_37: P2.37(PWM/GPIO_!) R70.2 R95.2 R98.2
NetP2_38: P2.38(PWM/GPIO_!) R66.2
NetP2_39: P2.39(PWM/GPIO_!) R54.2 R62.2
NetP2_40: P2.40(PWM/GPIO_!) R53.2 R60.2
NetQ2_1: Q2.1(G) R105.1
NetR108_2: R108.2 R112.2 U10.10(IN_C+)
NetR109_1: R109.1 U10.8(OUT_C) U10.9(IN_C-)
NetR110_2: R110.2 R113.2 U10.5(IN_B+)
NetR111_1: R111.1 U10.6(IN_B-) U10.7(OUT_B)
NetR116_2: R116.2 R122.2 U10.12(IN_D+)
NetR117_1: R117.1 U10.13(IN_D-) U10.14(OUT_D)
NetR119_2: R119.2 R123.2 U10.3(IN_A+)
NetR120_1: R120.1 U10.1(OUT_A) U10.2(IN_A-)

Not connected (* = marked no-connect by the designer): P2 17(GPIO)*

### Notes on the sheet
- BOOSTER PACK INTERFACE
- (near R53) For Antenna diversity
- (near R55) CC_COEX_BLE
- CC_COEX_SW_OUT
- (near R55) P58_GPIO_03 & P50_GPIO_00 can also be used for ANTSEL
- (near R59) P59_GPIO_04 / DIO 12 on CC2640R2LP (COEX_WAKEUP)
- (near R55) COEX_SW_OUT & CC_COEX_BLE_IN routed to ANTSEL on Diversity Board
- CC_COEX_WAKEUP
- Alternate I2C
- Alternate RTS
- Alternate CTS
- SWAP MOSI/MISO
- ADC DRIVER

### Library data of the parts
C35 = CMP-0006561-2: CAP, CERM, 0.01 uF, 10 V, +/- 10%, X5R, 0402; Manufacturer: MuRata; TaMin_C: -55°C; Polarized: N; SizeAreaWB_mm2: 3; Value1: Unknown; U/M: EA; Value: 0.01uF; TaMax_C: 85°C; SizeZ_mm: 0.6; SizeX_mm: 1; SizeY_mm: 0.5; Value2: 10V; CompType: Capacitor; Cap_F: 10nF; AEC Category: Q200
C36-C39 = CMP-0006639-2: CAP, CERM, 0.01 uF, 16 V, +/- 10%, X7R, 0402; Manufacturer: MuRata; TaMin_C: -55°C; Polarized: N; SizeAreaWB_mm2: 3; Value1: Unknown; U/M: EA; Value: 0.01uF; TaMax_C: 125°C; SizeZ_mm: 0.6; SizeX_mm: 1; SizeY_mm: 0.5; Value2: 16V; CompType: Capacitor; Cap_F: 10nF; AEC Category: Q200
J19 J20 = CMP-0002338-1: Header, 100mil, 3x1, Tin, TH; Manufacturer: Sullins Connector Solutions; CNHeader: TRUE; Current_A: 3A; Green_Lifecycle: Not Set; Shrouded: N; Gender: Male; Green_REACh: Incomplete; Voltage_V: 1.8kV; Row_Count: 1; Pitch_mm: 2.54; CT: FALSE; Cert_UL: Y
J21 = CMP-0054794-1: Header, 2.54 mm, 2x1, Gold, TH; PartNumber: 61300211121; Manufacturer: Wurth Elektronik; CNHeader: TRUE; Green_Lifecycle: Active; Green_REACh: Passed; CT: FALSE
J22 = CMP-0054794-1: Header, 2.54 mm, 2x1, Gold, TH; Manufacturer: Wurth Elektronik; CNHeader: TRUE; Green_Lifecycle: Active; Green_REACh: Passed; CT: FALSE
P1 = CMP-0003837-2: Receptacle, 2.54mm, 10x2, Tin, TH; Alternate PartNumber: CRD-081413-A-G; Manufacturer: Samtec; Alternate Manufacturer: Major League Electronics; Note: Booster Pack 40 pin J1 and J3; Green_Lifecycle: Active; Green_REACh: Incomplete
P2 = CMP-0078266-2: Receptacle, 2.54mm, 10x2, Tin, TH; Alternate PartNumber: CRD-081413-A-G; Manufacturer: Samtec; Alternate Manufacturer: Major League Electronics; Note: Booster Pack 40 pin J2 and J4; Green_REACh: Incomplete; Green_Lifecycle: Active
Q2 = CMP-0000059-2: MOSFET, P-CH, -30 V, -1.5 A, SSOT-3; Alternate Manufacturer: None; Manufacturer: Fairchild Semiconductor; SizeZ_mm: 1.12; ChType: P; Value2: 4 nC; Value1: 0; VdsMax_V: -30V; SizeX_mm: 2.92; SizeY_mm: 2.52; Vgs_V: -20V; Value: -30V; Rdson45_ohm: 2d; SizeArea_mm2: 7.3584; AEC Category: Q101; IdsMax_A: -1.5A; SizeAreaWB_mm2: 13.7984; U/M: EA; QgTyp_nC: 4
R53 R54 R59-R103 R106 R107 R114 R115 R118 R121 = CMP-0027004-2: RES, 0, 5%, 0.063 W, 0402; Manufacturer: Yageo America; Power_W: 63mW; TempCo: 200 ppm/C; Value_Code: 0000; U/M: EA; Value: 0; EIA_Code: E24; SizeX_mm: 1; SizeY_mm: 0.5; SizeZ_mm: 0.6; Value2: 0.063W; CompType: Resistor; VDC_V: 50V; AEC Category: Q200
R55 R56 = CMP-0026823-3: RES, 100 k, 5%, 0.063 W, AEC-Q200 Grade 0, 0402; PartNumber: CRCW0402100KJNED; Manufacturer: Vishay-Dale; CompType: Resistor; Value: 100k; Power_W: 63mW; Value2: 0.063W; VDC_V: 50V; TempCo: 200 ppm/C; EIA_Code: E24; SizeX_mm: 1; SizeY_mm: 0.5; SizeZ_mm: 0.6; AEC Qualified: Y; AEC Category: Q200; AEC Grade: 0
R57 R58 = CMP-0025874-3: RES, 0, 5%, 0.1 W, 0603; PartNumber: ERJ-3GEY0R00V; Manufacturer: Panasonic; Alternate Manufacturer: YAGEO; Alternate PartNumber: RC0603FR-070RL; CompType: Resistor; Value: 0; Value_Code: 0000; Power_W: 100mW; Value2: 0.1W; VDC_V: 50V; TempCo: 600 ppm/C; EIA_Code: E24; U/M: EA; AEC Category: Q200; SizeX_mm: 1.6; SizeY_mm: 0.8; SizeZ_mm: 1; SizeArea_mm2: 1.28
R104 R105 = CMP-0026992-3: as R38 on sheet MCU065E1_EngineArea
R108 R110 R116 R119 = CMP-0026455-2: RES, 576 k, 1%, 0.063 W, AEC-Q200 Grade 0, 0402; Manufacturer: Vishay-Dale; Power_W: 63mW; TempCo: 100 ppm/C; Value: 576k; EIA_Code: E96; SizeX_mm: 1; SizeY_mm: 0.5; SizeZ_mm: 0.6; Value2: 0.063W; CompType: Resistor; AEC Qualified: Y; VDC_V: 50V; AEC Category: Q200; AEC Grade: 0
R109 R111 R117 R120 = CMP-0026699-1: RES, 470, 1%, 0.1 W, AEC-Q200 Grade 0, 0402; Manufacturer: Panasonic; Power_W: 100mW; TempCo: 100 ppm/C; Value_Code: 470R; U/M: EA; Value: 470; SizeX_mm: 1; SizeY_mm: 0.5; SizeZ_mm: 0.6; Value2: 0.1W; CompType: Resistor; AEC Qualified: Y; VDC_V: 50V; AEC Grade: 0; AEC Category: Q200
R112 R113 R122 R123 = CMP-0026373-2: RES, 422 k, 1%, 0.063 W, AEC-Q200 Grade 0, 0402; Manufacturer: Vishay-Dale; Power_W: 63mW; TempCo: 100 ppm/C; Value: 422k; EIA_Code: E96; SizeX_mm: 1; SizeY_mm: 0.5; SizeZ_mm: 0.6; Value2: 0.063W; CompType: Resistor; AEC Qualified: Y; VDC_V: 50V; AEC Category: Q200; AEC Grade: 0
TP2 = CMP-0055152-1: Test Point, Miniature, SMT; Manufacturer: Keystone; CNHeader: FALSE; Green_Lifecycle: Active; Green_REACh: Passed; CT: TRUE
U10 = CMP-0041122-1: Low Cost, Low Power, Rail-to-Rail Operational Amplifier MicroAmplifier(TM) Series, 2.7 to 5.5 V, -55 to 125 degC, 14-pin SOP (PW14), Green (RoHS & no Sb/Br); Manufacturer: Texas Instruments; IIB(Max)(pA): 10; CMRR(Min)(dB): 76; Vio (25C)(Max)(mV): 6; Total Supply Voltage(Min)(+5V is 5, +/-5V is 10): 2.7; Total Supply Voltage(Max)(+5V is 5, +/-5V is 10): 5.5; Rating: Catalog; Offset Drift(Typ)(uV/C): 3; Number of Channels: 4; GBW(Typ)(MHz): 1; Sub Family: Low Input Bias Current Amp (<=10pA), Low Power Amp (<=500uA), Low Supply Voltage Amplifier (<=2.7V), Precision Amplifier; Iq per channel(Max)(mA): 0.25; Packing: SMALL T&R

## Sheet MCU065E1_LEDs_Switches_Sensors.SchDoc: LEDs_Switches_Sensors
size 431 x 279 mm; Date: Not shown in title block; ApprovedBy: Not shown in title block; CheckedBy: Not shown in title block; Author: Not shown in title block; CompanyName: Not shown in title block; DrawnBy: Seong Kim; Engineer: Not shown in title block; Organization: Not shown in title block; Address1: Not shown in title block; Address2: Not shown in title block; Address3: Not shown in title block; Address4: Not shown in title block; DocumentNumber: 4; Revision: Use project parameter SCH_Rev; SheetNumber: 4; SheetTotal: 6; PageSetup: Record=PageOptions¦CenterHorizontal=True¦CenterVertical=True¦PrintScale=1.00¦XCorrection=1.00¦YCorrection=1.00¦PrintKind=0¦BorderSize=5000000¦LeftOffset=0¦BottomOffset=0¦Orientation=2¦PaperLength=1000¦PaperWidth=1000¦Scale=100¦PaperSource=15¦PrintQuality=600¦MediaType=1¦DitherType=10¦PaperKind=Letter¦PrintScaleMode=1
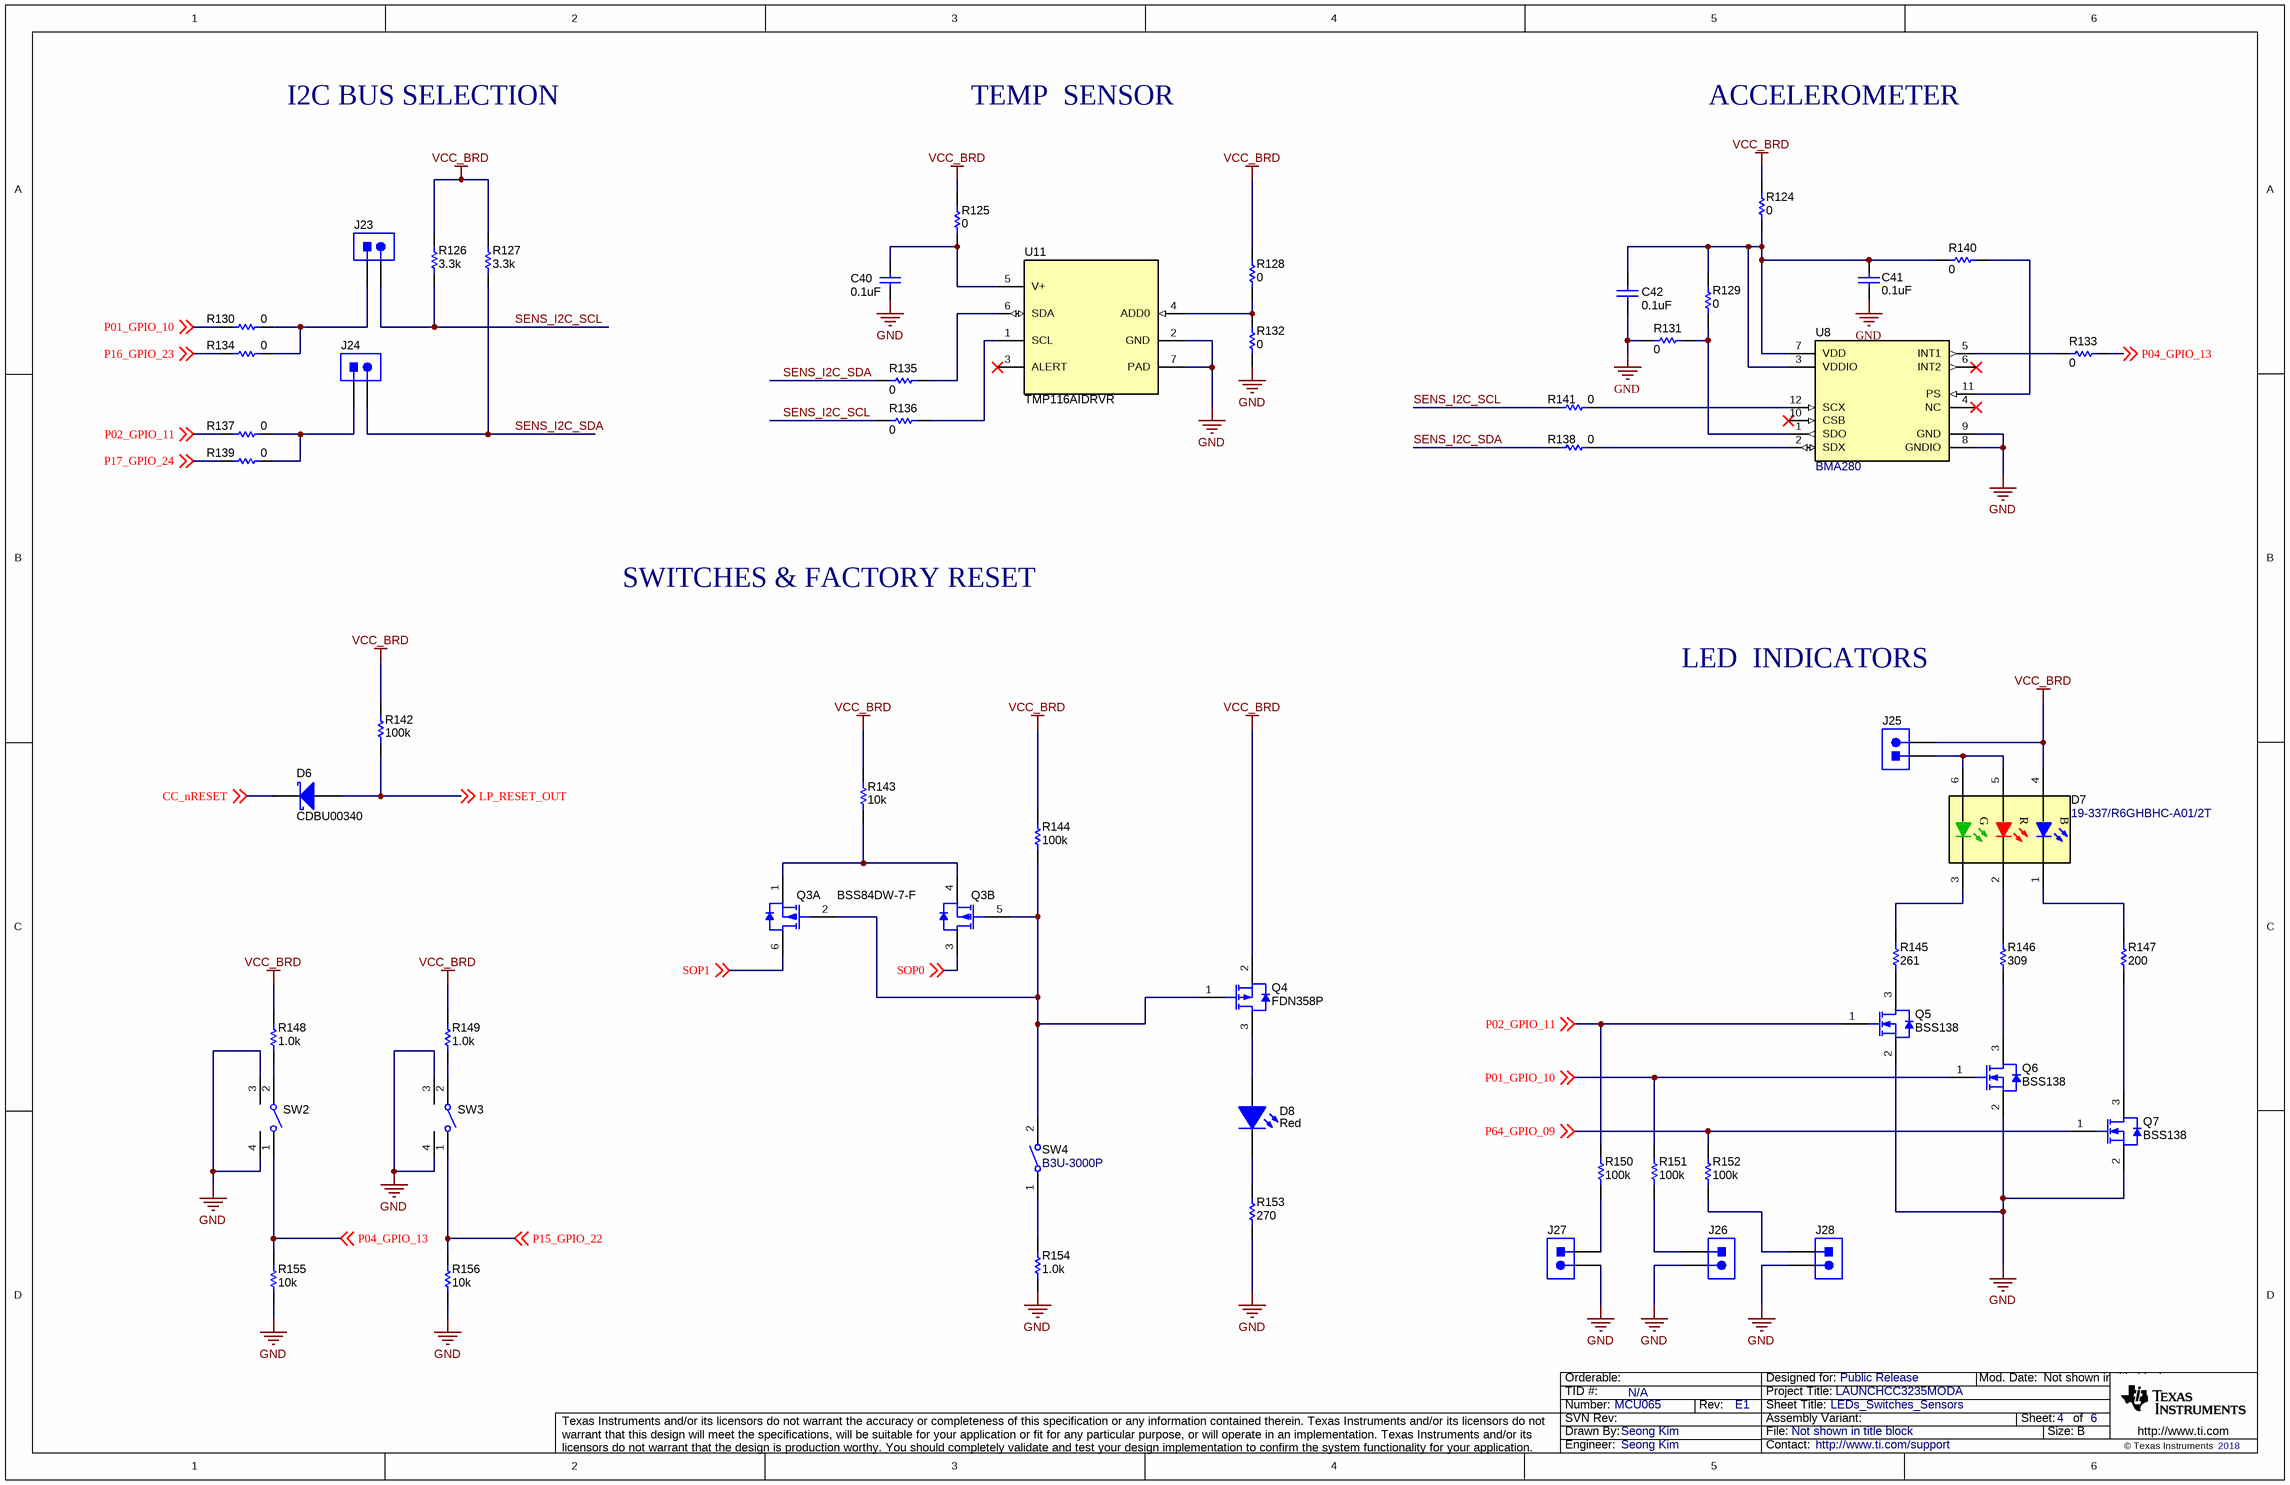
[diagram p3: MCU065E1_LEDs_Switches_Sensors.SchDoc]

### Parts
C40  ValueDisplayed: 0.1uF  [0402]  (hidden comment: GRM155R61A104KA01D)
C41  ValueDisplayed: 0.1uF  [0402]  (hidden comment: GRM155R61A104KA01D)
C42  ValueDisplayed: 0.1uF  [0402]  (hidden comment: GRM155R61A104KA01D)
D6  CDBU00340  [SOD-523F]
D7  19-337/R6GHBHC-A01/2T  [19-337_RGB]
D8  value Red  [SML-31_Red]  (hidden comment: CMP-0002871-1)
J23  61300211121  [WURTH_61300211121]  (value not drawn)
J24  61300211121  [WURTH_61300211121]  (value not drawn)
J25  CMP-0054794-1  [WURTH_61300211121]  (value not drawn)
J26  61300211121  [WURTH_61300211121]  (value not drawn)
J27  61300211121  [WURTH_61300211121]  (value not drawn)
J28  61300211121  [WURTH_61300211121]  (value not drawn)
Q3  BSS84DW-7-F  [SOT-363]  (parts A,B of 2)
Q4  FDN358P  [SSOT-3]
Q5  BSS138  [SOT-23]
Q6  BSS138  [SOT-23]
Q7  BSS138  [SOT-23]
R124  ValueDisplayed: 0  [0402]  (hidden comment: ERJ-2GE0R00X)
R125  ValueDisplayed: 0  [0402]  (hidden comment: ERJ-2GE0R00X)
R126  ValueDisplayed: 3.3k  [0402]  (hidden comment: CRCW04023K30JNED)
R127  ValueDisplayed: 3.3k  [0402]  (hidden comment: CRCW04023K30JNED)
R128  ValueDisplayed: 0  [0402]  (hidden comment: ERJ-2GE0R00X)
R129  ValueDisplayed: 0  [0402]  (hidden comment: ERJ-2GE0R00X)
R130  ValueDisplayed: 0  [0402]  (hidden comment: ERJ-2GE0R00X)
R131  ValueDisplayed: 0  [0402]  (hidden comment: ERJ-2GE0R00X)
R132  ValueDisplayed: 0  [0402]  (hidden comment: ERJ-2GE0R00X)
R133  ValueDisplayed: 0  [0402]  (hidden comment: ERJ-2GE0R00X)
R134  ValueDisplayed: 0  [0402]  (hidden comment: ERJ-2GE0R00X)
R135  ValueDisplayed: 0  [0402]  (hidden comment: ERJ-2GE0R00X)
R136  ValueDisplayed: 0  [0402]  (hidden comment: ERJ-2GE0R00X)
R137  ValueDisplayed: 0  [0402]  (hidden comment: ERJ-2GE0R00X)
R138  ValueDisplayed: 0  [0402]  (hidden comment: ERJ-2GE0R00X)
R139  ValueDisplayed: 0  [0402]  (hidden comment: ERJ-2GE0R00X)
R140  ValueDisplayed: 0  [0402]  (hidden comment: ERJ-2GE0R00X)
R141  ValueDisplayed: 0  [0402]  (hidden comment: ERJ-2GE0R00X)
R142  ValueDisplayed: 100k  [0402]  (hidden comment: CRCW0402100KJNED)
R143  ValueDisplayed: 10k  [0402]  (hidden comment: CRCW040210K0JNED)
R144  ValueDisplayed: 100k  [0402]  (hidden comment: ERJ-2RKF1003X)
R145  ValueDisplayed: 261  [0402]  (hidden comment: CRCW0402261RFKED)
R146  ValueDisplayed: 309  [0402]  (hidden comment: CRCW0402309RFKED)
R147  ValueDisplayed: 200  [0402]  (hidden comment: CRCW0402200RJNED)
R148  ValueDisplayed: 1.0k  [0402]  (hidden comment: CRCW04021K00JNED)
R149  ValueDisplayed: 1.0k  [0402]  (hidden comment: CRCW04021K00JNED)
R150  ValueDisplayed: 100k  [0402]  (hidden comment: CRCW0402100KJNED)
R151  ValueDisplayed: 100k  [0402]  (hidden comment: CRCW0402100KJNED)
R152  ValueDisplayed: 100k  [0402]  (hidden comment: CRCW0402100KJNED)
R153  ValueDisplayed: 270  [0603]  (hidden comment: CRCW0603270RJNEA)
R154  ValueDisplayed: 1.0k  [0402]  (hidden comment: CRCW04021K00JNED)
R155  ValueDisplayed: 10k  [0402]  (hidden comment: CRCW040210K0JNED)
R156  ValueDisplayed: 10k  [0402]  (hidden comment: CRCW040210K0JNED)
SW2  TL3330AF260QG  [SW_TL3330]  (value not drawn)
SW3  TL3330AF260QG  [SW_TL3330]  (value not drawn)
SW4  B3U-3000P  [SW_B3U-3000P]
U8  BMA280  [12LGA]
U11  TMP116AIDRVR  [DRV0006A]

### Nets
GND: C40.2 C41.2 C42.2 J26.2 J27.2 J28.2 Q5.2(S) Q6.2(S) Q7.2(S) R131.2 R132.1 R153.1 R154.1 R155.1 R156.1 SW2.3 SW2.4 SW3.3 SW3.4 U8.8(GNDIO) U8.9(GND) U11.2(GND) U11.7(PAD)
VCC_BRD: D7.4(A) J25.2 Q4.2(S) R124.1 R125.2 R126.2 R127.2 R128.2 R142.2 R143.2 R144.2 R148.2 R149.2
CC_nRESET: D6.1(K) ; off-sheet CC_nRESET
LP_RESET_OUT: D6.2(A) R142.1 ; off-sheet LP_RESET_OUT
P01_GPIO_10: Q6.1(G) R130.1 R151.2 ; off-sheet P01_GPIO_10
P02_GPIO_11: Q5.1(G) R137.1 R150.2 ; off-sheet P02_GPIO_11
P04_GPIO_13: R133.1 R155.2 SW2.1 ; off-sheet P04_GPIO_13
P15_GPIO_22: R156.2 SW3.1 ; off-sheet P15_GPIO_22
P16_GPIO_23: R134.1 ; off-sheet P16_GPIO_23
P17_GPIO_24: R139.1 ; off-sheet P17_GPIO_24
P64_GPIO_09: Q7.1(G) R152.2 ; off-sheet P64_GPIO_09
SENS_I2C_SCL: J23.2 R126.1 R136.2 R141.2
SENS_I2C_SDA: J24.2 R127.1 R135.2 R138.2
SOP0: Q3.3(D) ; off-sheet SOP0
SOP1: Q3.6(D) ; off-sheet SOP1
NetC40_1: C40.1 R125.1 U11.5(V+)
NetC41_1: C41.1 C42.1 R124.2 R129.2 R140.2 U8.3(VDDIO) U8.7(VDD)
NetD7_1: D7.1(K) R147.2
NetD7_2: D7.2(K) R146.2
NetD7_3: D7.3(K) R145.2
NetD7_5: D7.5(A) D7.6(A) J25.1
NetD8_1: D8.1(K) R153.2
NetD8_2: D8.2(A) Q4.3(D)
NetJ23_1: J23.1 R130.2 R134.2
NetJ24_1: J24.1 R137.2 R139.2
NetJ26_1: J26.1 R151.1
NetJ27_1: J27.1 R150.1
NetJ28_1: J28.1 R152.1
NetQ3_1: Q3.1(S) Q3.4(S) R143.1
NetQ3_2: Q3.2(G) Q3.5(G) Q4.1(G) R144.1 SW4.2
NetQ5_3: Q5.3(D) R145.1
NetQ6_3: Q6.3(D) R146.1
NetQ7_3: Q7.3(D) R147.1
NetR128_1: R128.1 R132.2 U11.4(ADD0)
NetR129_1: R129.1 R131.1 U8.1(SDO)
NetR133_2: R133.2 U8.5(INT1)
NetR135_1: R135.1 U11.6(SDA)
NetR136_1: R136.1 U11.1(SCL)
NetR138_1: R138.1 U8.2(SDX)
NetR140_1: R140.1 U8.11(PS)
NetR141_1: R141.1 U8.12(SCX)
NetR148_1: R148.1 SW2.2
NetR149_1: R149.1 SW3.2
NetR154_2: R154.2 SW4.1

Not connected (* = marked no-connect by the designer): U8 4(NC)* 6(INT2)* 10(CSB)*; U11 3(ALERT)*

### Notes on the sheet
- I2C BUS SELECTION
- TEMP  SENSOR
- ACCELEROMETER
- SWITCHES & FACTORY RESET
- LED  INDICATORS

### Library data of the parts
C40-C42 = CMP-0006562-2: as C31 on sheet MCU065E1_EngineArea
D6 = CMP-0081923-1: as D5 on sheet MCU065E1_EngineArea
D7 = CMP-0074720-2: LED, RGB, TH; Manufacturer: Everlight; Vf_V: 3.8V; Ir_A: 50µA; Io_A: 25mA; Vr_V: 5V; Angle: 120.0; Tjmax_C: 85°C
D8 = CMP-0002871-1: LED, Red, SMD; Manufacturer: Rohm; PartNumber: SML-311UTT86; Alternate Manufacturer: Everlight; Alternate PartNumber: 19-217/R6C-AL1M2VY/3T; Type: AlInGaP; Vf_V: 1.8V; Io_A: 2mA; Value1: W; U/M: EA
J23 J24 J26-J28 = CMP-0054794-1: as J22 on sheet MCU065E1_Host_Interface
J25 = CMP-0054794-1: as J21 on sheet MCU065E1_Host_Interface
Q3 = CMP-0000014-2: MOSFET, 2-CH, P-CH, -50 V, -0.13 A, AEC-Q101, SOT-363; Alternate Manufacturer: None; Manufacturer: Diodes Inc.; SizeZ_mm: 1.1; ChType: P; VdsMax_V: -50V; SizeX_mm: 2.2; Vgs_V: -20V; AEC Qualified: Y; Value: -50V; SizeArea_mm2: 4.84; AEC Category: Q101; IdsMax_A: -1.3dA; SizeAreaWB_mm2: 10.24; U/M: EA
Q4 = CMP-0000059-2: as Q2 on sheet MCU065E1_Host_Interface
Q5-Q7 = CMP-0000755-1: MOSFET, N-CH, 50 V, 0.22 A, SOT-23; Alternate Manufacturer: None; Manufacturer: Fairchild Semiconductor; SizeZ_mm: 1.1; ChType: N; Value2: 1.7 nC; VdsMax_V: 50V; SizeX_mm: 2.5; SizeY_mm: 3; Vgs_V: 20V; Value: 50V; Rdson45_ohm: 6; SizeArea_mm2: 7.5; AEC Category: Q101; IdsMax_A: 2.2dA; SizeAreaWB_mm2: 14; U/M: EA; QgTyp_nC: 1.7
R124 R131 R133 R138 R140 R141 = CMP-0026992-3: RES, 0, 5%, 0.1 W, AEC-Q200 Grade 0, 0402; Manufacturer: Panasonic; Power_W: 100mW; TempCo: 600 ppm/C; Value_Code: 0000; Value: 0; EIA_Code: E24; SizeX_mm: 1; SizeY_mm: 0.5; SizeZ_mm: 0.6; Value2: 0.1W; AEC Qualified: Y; VDC_V: 50V; AEC Category: Q200; SizeAreaWB_mm2: 3
R125 R128-R130 R132 R134-R137 R139 = CMP-0026992-3: as R38 on sheet MCU065E1_EngineArea
R126 R127 = CMP-0026918-5: RES, 3.3 k, 5%, 0.063 W, AEC-Q200 Grade 0, 0402; Manufacturer: Vishay-Dale; Power_W: 63mW; TempCo: 200 ppm/C; Value_Code: 3k30; Value: 3.3k; EIA_Code: E24; SizeX_mm: 1; SizeY_mm: 0.5; SizeZ_mm: 0.6; Value2: 0.063W; AEC Qualified: Y; VDC_V: 50V; AEC Category: Q200; AEC Grade: 0
R142 R150-R152 = CMP-0026823-3: as R47 on sheet MCU065E1_EngineArea
R143 = CMP-0026825-5: as R49 on sheet MCU065E1_EngineArea
R144 = CMP-0026659-1: RES, 100 k, 1%, 0.1 W, 0402; Manufacturer: Panasonic; Power_W: 100mW; TempCo: 100 ppm/C; U/M: EA; Value: 100k; EIA_Code: E96; SizeX_mm: 1; SizeY_mm: 0.5; SizeZ_mm: 0.6; Value2: 0.1W; VDC_V: 50V; AEC Category: Q200
R145 = CMP-0026204-2: RES, 261, 1%, 0.063 W, AEC-Q200 Grade 0, 0402; Manufacturer: Vishay-Dale; Power_W: 63mW; TempCo: 100 ppm/C; Value_Code: 261R; Value: 261; EIA_Code: E96; SizeX_mm: 1; SizeY_mm: 0.5; SizeZ_mm: 0.6; Value2: 0.063W; AEC Qualified: Y; VDC_V: 50V; AEC Category: Q200; AEC Grade: 0
R146 = CMP-0026283-2: RES, 309, 1%, 0.063 W, AEC-Q200 Grade 0, 0402; Manufacturer: Vishay-Dale; Power_W: 63mW; TempCo: 100 ppm/C; Value_Code: 309R; Value: 309; EIA_Code: E96; SizeX_mm: 1; SizeY_mm: 0.5; SizeZ_mm: 0.6; Value2: 0.063W; AEC Qualified: Y; VDC_V: 50V; AEC Category: Q200; AEC Grade: 0
R147 = CMP-0026874-3: RES, 200, 5%, 0.063 W, AEC-Q200 Grade 0, 0402; Manufacturer: Vishay-Dale; Power_W: 63mW; TempCo: 200 ppm/C; Value_Code: 200R; Value: 200; EIA_Code: E24; SizeX_mm: 1; SizeY_mm: 0.5; SizeZ_mm: 0.6; Value2: 0.063W; AEC Qualified: Y; VDC_V: 50V; AEC Category: Q200; AEC Grade: 0
R148 R149 R154 = CMP-0026852-3: RES, 1.0 k, 5%, 0.063 W, AEC-Q200 Grade 0, 0402; Manufacturer: Vishay-Dale; Power_W: 63mW; TempCo: 200 ppm/C; Value_Code: 1k00; Value: 1.0k; EIA_Code: E24; Res_ohm: 1k; SizeX_mm: 1; SizeY_mm: 0.5; SizeZ_mm: 0.6; Value2: 0.063W; AEC Qualified: Y; VDC_V: 50V; AEC Category: Q200; AEC Grade: 0
R153 = CMP-0025765-4: RES, 270, 5%, 0.1 W, AEC-Q200 Grade 0, 0603; Manufacturer: Vishay-Dale; Power_W: 100mW; TempCo: 200 ppm/C; Value_Code: 270R; Value: 270; EIA_Code: E24; SizeX_mm: 1.6; SizeY_mm: 0.8; SizeZ_mm: 1; Value2: 0.1W; SizeArea_mm2: 1.28; AEC Qualified: Y; VDC_V: 75V; AEC Category: Q200; AEC Grade: 0
R155 R156 = CMP-0026825-5: RES, 10 k, 5%, 0.063 W, AEC-Q200 Grade 0, 0402; Manufacturer: Vishay-Dale; Power_W: 63mW; TempCo: 200 ppm/C; Value_Code: 10k0; Value: 10k; EIA_Code: E24; SizeX_mm: 1; SizeY_mm: 0.5; SizeZ_mm: 0.6; Value2: 0.063W; AEC Qualified: Y; VDC_V: 50V; AEC Category: Q200; AEC Grade: 0
SW2 SW3 = CMP-0002231-1: Switch, SPST-NO,  1 Pos, 0.05A, 12VDC, SMD; Manufacturer: E-Switch; CurrentRating_mA: 50A; PositionCount: 1; VDC_V: 12V; SwitchFunction: Off-Mom
SW4 = CMP-0076764-1: Switch, SPST-NO, Off-Mom, 0.05 A, 12 VDC, SMT; Manufacturer: Omron Electronic Components; VDC_V: 12V; PositionCount: 1.0; CurrentRating_mA: 50A; SizeAreaWB_mm2: 21.0; SizeArea_mm2: 12.8; SizeX_mm: 3.2; SizeY_mm: 4.0; SizeZ_mm: 1.35
U8 = CMP-0004812-1: 14 Bit, Digital, Triaxial Acceleration Sensor with Intelligent On-Chip Motion-Triggered Interrupt Controller, 12LGA; Manufacturer: Bosch Solar Energy
U11 = CMP-0013432-6: High-Accuracy, Low-Power, Digital Temperature Sensor with SMBus and Two-Wire Serial Interface, DRV0006A (WSON-6); Manufacturer: Texas Instruments; Alternate PartNumber: TMP116AIDRVT; SizeX_mm: 2; CompType: IC; SizeZ_mm: 0.8; SizeArea_mm2: 4; SizeAreaWB_mm2: 9; U/M: EA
